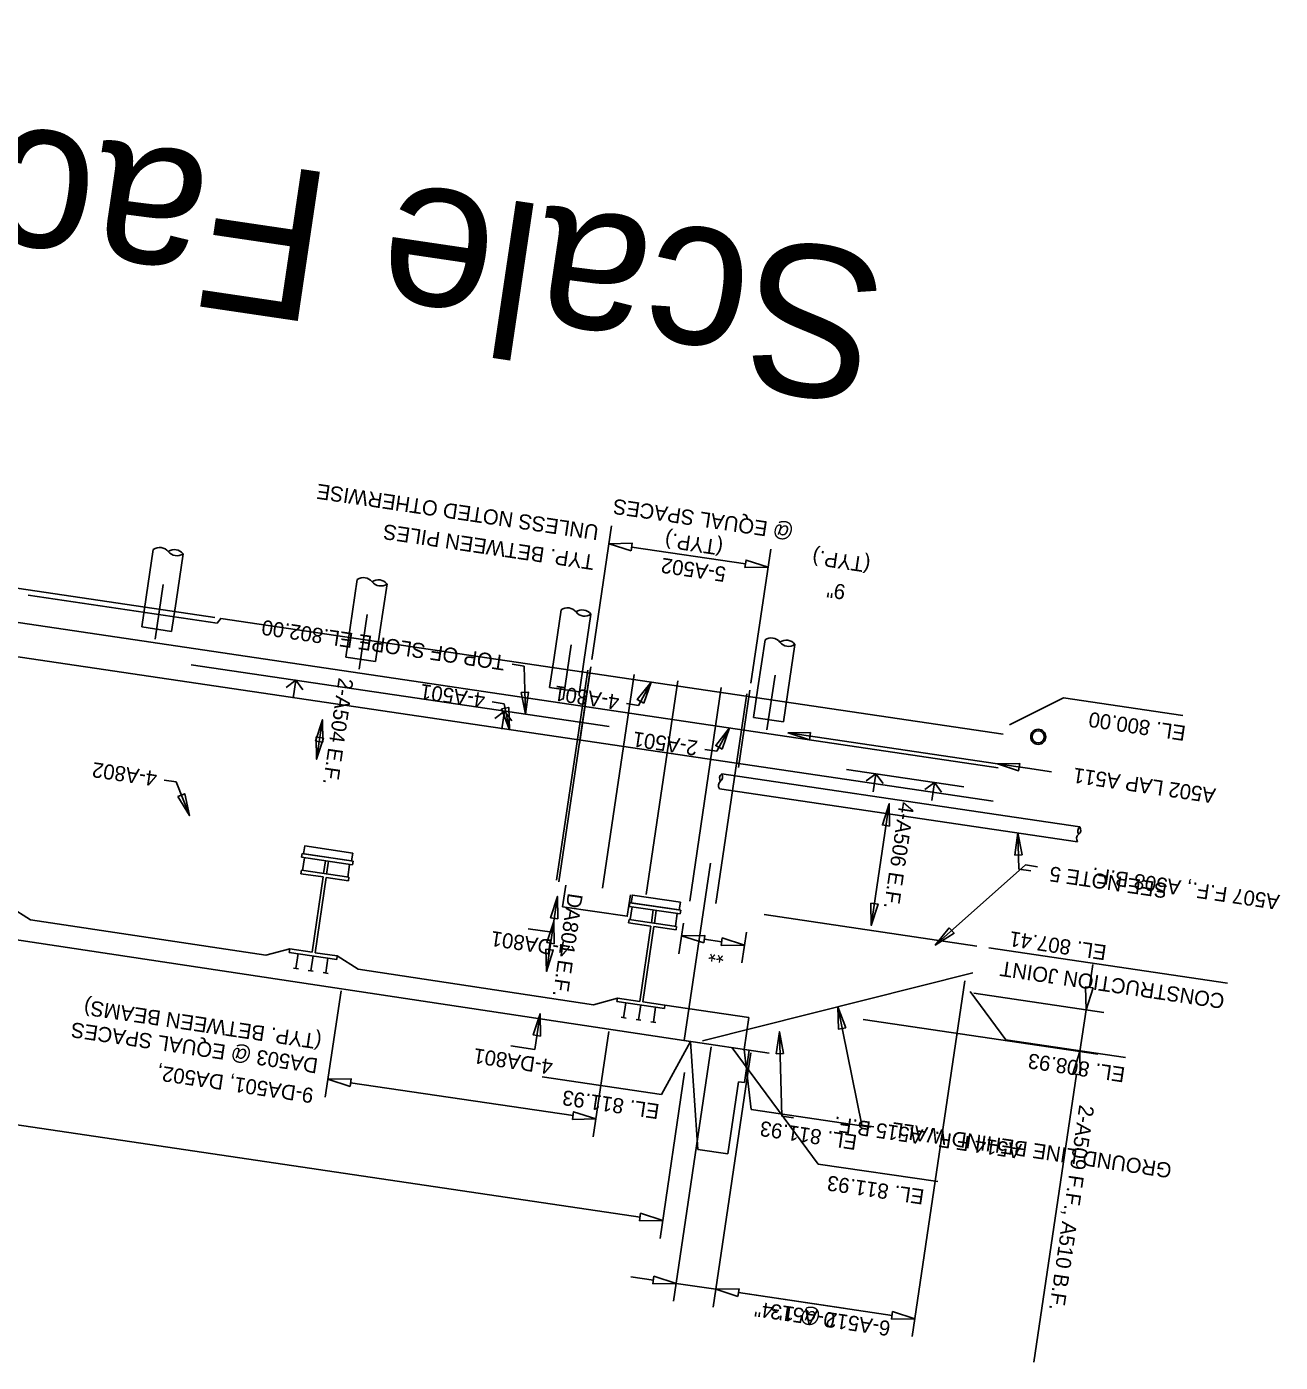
# Model space of a CAD drawing. Extents: x 1468952 to 1470054, y 573916 to 574214.
# Drawn here: x 1469049.93 to 1469091.48, y 574051.68 to 574095.95 of the extents above; entities that cross this region are included whole.
import ezdxf

# ---------------------------------------------------------------- set-up
doc = ezdxf.new("R2010")
doc.units = 0
for name, color, linetype in [('BR_P_Beam_Object', 7, 'Continuous'), ('BR_P_Beam_Stl_Det', 7, 'Continuous'), ('BR_P_Gen_Centerline', 7, 'Continuous'), ('BR_P_Gen_Phase_Construction', 7, 'Continuous'), ('BR_P_Sub_Centerline', 7, 'Continuous'), ('BR_P_Sub_Deep_Centerline', 7, 'Continuous'), ('BR_P_Sub_Foot_Centerline', 7, 'Continuous'), ('BR_X_SV_Beam_Seat', 7, 'Continuous'), ('Default', 7, 'Continuous'), ('GE_P_CL_50', 7, 'Continuous'), ('GK_Cells', 7, 'Continuous'), ('PF_X_Ground_Line', 7, 'Continuous'), ('PV_X_EOP', 7, 'Continuous'), ('SV_X_Text_Elevation', 7, 'Continuous'), ('UT_X_Water', 7, 'Continuous')]:
    doc.layers.add(name, color=color, linetype=linetype)

# ---------------------------------------------------------------- blocks, each defined once
blk = doc.blocks.new('arrowOhio')
at = {"layer": 'Default'}
blk.add_lwpolyline([(0.00381, 0.000635), (0.00381, -0.000635), (0, 0)], close=True, dxfattribs=at)

msp = doc.modelspace()

# ---------------------------------------------------------------- linework, layer by layer
at = {"layer": 'BR_P_Beam_Object'}
for p, q in [((1469082.065, 574069.842), (1469072.965, 574071.189)), ((1469081.992, 574069.347), (1469072.891, 574070.694)), ((1469072.33, 574062.337), (1469081.288, 574064.593))]:
    msp.add_line(p, q, dxfattribs=at)
for centre, start, end in [((1469073.04, 574070.799), 127.976, 215.1816), ((1469073.076, 574071.046), 127.976, 215.1816), ((1469072.817, 574071.085), 307.976, 35.1816)]:
    msp.add_arc(centre, 0.181, start, end, dxfattribs=at)
at = {"layer": 'BR_P_Beam_Stl_Det'}
for p, q in [((1469068.524, 574074.626), (1469067.494, 574067.667)), ((1469068.619, 574074.697), (1469067.57, 574067.614)), ((1469068.625, 574074.738), (1469068.247, 574072.182)), ((1469070.063, 574074.483), (1469069.014, 574067.4)), ((1469071.507, 574074.269), (1469070.458, 574067.186)), ((1469072.951, 574074.055), (1469071.903, 574066.972)), ((1469073.901, 574073.957), (1469073.522, 574071.401)), ((1469073.8, 574073.845), (1469072.77, 574066.886))]:
    msp.add_line(p, q, dxfattribs=at)
for points in [[(1469056.161, 574076.372), (1469030.427, 574080.182), (1469030.303, 574080.026), (1469024.038, 574080.953)], [(1469082.126, 574071.391), (1469046.506, 574076.665), (1469046.433, 574076.85), (1469043.3, 574077.314)], [(1469082.291, 574072.504), (1469056.359, 574076.343), (1469056.235, 574076.186), (1469049.97, 574077.114)], [(1469081.962, 574070.278), (1469046.341, 574075.552), (1469046.268, 574075.738), (1469043.135, 574076.201)]]:
    msp.add_lwpolyline(points, dxfattribs=at)
at = {"layer": 'BR_P_Gen_Centerline'}
for p, q in [((1469082.065, 574069.842), (1469084.835, 574069.432)), ((1469081.992, 574069.347), (1469084.762, 574068.937))]:
    msp.add_line(p, q, dxfattribs=at)
for radius in [0.25, 0.2]:
    msp.add_circle((1469083.457, 574072.416), radius, dxfattribs=at)
for centre, start, end in [((1469084.91, 574069.041), 127.976, 215.1816), ((1469084.947, 574069.289), 127.976, 215.1816), ((1469084.687, 574069.327), 307.976, 35.1816)]:
    msp.add_arc(centre, 0.181, start, end, dxfattribs=at)
at = {"layer": 'BR_P_Gen_Phase_Construction'}
for p, q in [((1469053.887, 574077.046), (1469054.122, 574078.629)), ((1469054.877, 574076.9), (1469055.111, 574078.482)), ((1469060.647, 574076.045), (1469060.881, 574077.628)), ((1469061.636, 574075.899), (1469061.871, 574077.482)), ((1469067.407, 574075.045), (1469067.641, 574076.627)), ((1469068.396, 574074.898), (1469068.63, 574076.481)), ((1469074.166, 574074.044), (1469074.401, 574075.627)), ((1469075.155, 574073.897), (1469075.39, 574075.48))]:
    msp.add_line(p, q, dxfattribs=at)
for centre, start, end in [((1469054.331, 574078.332), 37.976, 125.1816), ((1469054.825, 574078.259), 37.976, 125.1816), ((1469054.902, 574078.779), 217.976, 305.1816), ((1469061.09, 574077.332), 37.976, 125.1816), ((1469061.585, 574077.258), 37.976, 125.1816), ((1469061.662, 574077.778), 217.976, 305.1816), ((1469067.85, 574076.331), 37.976, 125.1816), ((1469068.344, 574076.258), 37.976, 125.1816), ((1469068.421, 574076.777), 217.976, 305.1816), ((1469074.609, 574075.33), 37.976, 125.1816), ((1469075.104, 574075.257), 37.976, 125.1816), ((1469075.181, 574075.776), 217.976, 305.1816)]:
    msp.add_arc(centre, 0.362, start, end, dxfattribs=at)
at = {"layer": 'BR_P_Sub_Centerline'}
for p, q in [((1469053.741, 574076.057), (1469053.887, 574077.046)), ((1469054.877, 574076.9), (1469054.73, 574075.91)), ((1469054.73, 574075.91), (1469053.741, 574076.057)), ((1469060.501, 574075.056), (1469060.647, 574076.045)), ((1469061.636, 574075.899), (1469061.49, 574074.91)), ((1469061.49, 574074.91), (1469060.501, 574075.056)), ((1469067.26, 574074.055), (1469067.407, 574075.045)), ((1469068.396, 574074.898), (1469068.249, 574073.909)), ((1469068.249, 574073.909), (1469067.26, 574074.055)), ((1469074.02, 574073.055), (1469074.166, 574074.044)), ((1469075.155, 574073.897), (1469075.009, 574072.908)), ((1469075.009, 574072.908), (1469074.02, 574073.055))]:
    msp.add_line(p, q, dxfattribs=at)
at = {"layer": 'BR_P_Sub_Deep_Centerline'}
for q in [(1469072.594, 574068.231), (1469074.541, 574061.928)]:
    msp.add_line((1469071.723, 574062.345), q, dxfattribs=at)
at = {"layer": 'BR_P_Sub_Foot_Centerline'}
for p, q in [((1469059.073, 574067.986), (1469059.136, 574068.409)), ((1469059.77, 574067.883), (1469059.833, 574068.306)), ((1469059.869, 574067.868), (1469059.932, 574068.291)), ((1469060.566, 574067.765), (1469060.629, 574068.188)), ((1469069.936, 574066.358), (1469069.998, 574066.78)), ((1469070.633, 574066.255), (1469070.695, 574066.677)), ((1469070.732, 574066.24), (1469070.794, 574066.663)), ((1469071.429, 574066.137), (1469071.491, 574066.559))]:
    msp.add_line(p, q, dxfattribs=at)
at = {"layer": 'BR_X_SV_Beam_Seat'}
for p, q in [((1469069.23, 574072.753), (1469055.381, 574074.803)), ((1469058.844, 574074.29), (1469058.522, 574074.052)), ((1469058.844, 574074.29), (1469058.756, 574073.697)), ((1469058.844, 574074.29), (1469059.082, 574073.969)), ((1469065.768, 574073.265), (1469065.447, 574073.027)), ((1469065.768, 574073.265), (1469065.68, 574072.672)), ((1469065.768, 574073.265), (1469066.006, 574072.944)), ((1469080.988, 574070.759), (1469077.107, 574071.334)), ((1469078.078, 574071.19), (1469077.756, 574070.952)), ((1469078.078, 574071.19), (1469077.99, 574070.597)), ((1469078.078, 574071.19), (1469078.316, 574070.869)), ((1469080.018, 574070.903), (1469079.697, 574070.665)), ((1469080.018, 574070.903), (1469079.93, 574070.309)), ((1469080.018, 574070.903), (1469080.256, 574070.582)), ((1469081.815, 574065.421), (1469089.729, 574064.249))]:
    msp.add_line(p, q, dxfattribs=at)
msp.add_lwpolyline([(1469069.941, 574067.179), (1469069.836, 574066.468), (1469067.692, 574066.785), (1469067.798, 574067.496)], dxfattribs=at)
at = {"layer": 'GE_P_CL_50'}
for p, q in [((1469059.145, 574068.797), (1469059.107, 574068.539)), ((1469059.039, 574068.423), (1469059.057, 574068.547)), ((1469060.726, 574068.173), (1469059.039, 574068.423)), ((1469059.057, 574068.547), (1469060.744, 574068.297)), ((1469060.733, 574068.562), (1469060.694, 574068.304)), ((1469060.744, 574068.297), (1469060.726, 574068.173)), ((1469069.901, 574066.795), (1469069.92, 574066.918)), ((1469069.92, 574066.918), (1469071.606, 574066.669)), ((1469070.007, 574067.169), (1469069.969, 574066.911)), ((1469071.595, 574066.934), (1469071.557, 574066.676)), ((1469071.588, 574066.545), (1469069.901, 574066.795)), ((1469071.606, 574066.669), (1469071.588, 574066.545))]:
    msp.add_line(p, q, dxfattribs=at)
for points in [[(1469060.733, 574068.562), (1469060.694, 574068.304), (1469059.107, 574068.539), (1469059.145, 574068.797)], [(1469071.595, 574066.934), (1469071.557, 574066.676), (1469069.969, 574066.911), (1469070.007, 574067.169)]]:
    msp.add_lwpolyline(points, close=True, dxfattribs=at)
at = {"layer": 'GK_Cells'}
for p, q in [((1469059.015, 574067.879), (1469059.032, 574067.992)), ((1469059.753, 574067.77), (1469059.015, 574067.879)), ((1469059.032, 574067.992), (1469060.607, 574067.759)), ((1469059.384, 574065.276), (1469059.753, 574067.77)), ((1469059.853, 574067.755), (1469059.483, 574065.261)), ((1469060.591, 574067.646), (1469059.853, 574067.755)), ((1469060.607, 574067.759), (1469060.591, 574067.646)), ((1469069.878, 574066.251), (1469069.895, 574066.364)), ((1469070.616, 574066.141), (1469069.878, 574066.251)), ((1469069.895, 574066.364), (1469071.47, 574066.131)), ((1469070.247, 574063.648), (1469070.616, 574066.141)), ((1469070.715, 574066.127), (1469070.346, 574063.633)), ((1469071.453, 574066.018), (1469070.715, 574066.127)), ((1469071.47, 574066.131), (1469071.453, 574066.018)), ((1469058.629, 574065.272), (1469058.646, 574065.385)), ((1469060.205, 574065.039), (1469058.629, 574065.272)), ((1469058.646, 574065.385), (1469059.384, 574065.276)), ((1469058.922, 574065.229), (1469058.849, 574064.734)), ((1469059.417, 574065.155), (1469059.344, 574064.661)), ((1469059.483, 574065.261), (1469060.221, 574065.152)), ((1469059.912, 574065.082), (1469059.838, 574064.588)), ((1469060.221, 574065.152), (1469060.205, 574065.039)), ((1469058.932, 574064.722), (1469058.767, 574064.746)), ((1469059.426, 574064.649), (1469059.261, 574064.673)), ((1469059.921, 574064.575), (1469059.756, 574064.6)), ((1469069.492, 574063.644), (1469069.509, 574063.757)), ((1469069.509, 574063.757), (1469070.247, 574063.648)), ((1469071.067, 574063.411), (1469069.492, 574063.644)), ((1469069.785, 574063.6), (1469069.712, 574063.106)), ((1469070.279, 574063.527), (1469070.206, 574063.033)), ((1469070.346, 574063.633), (1469071.084, 574063.524)), ((1469070.774, 574063.454), (1469070.701, 574062.959)), ((1469071.084, 574063.524), (1469071.067, 574063.411)), ((1469069.794, 574063.094), (1469069.629, 574063.118)), ((1469070.289, 574063.02), (1469070.124, 574063.045)), ((1469070.783, 574062.947), (1469070.618, 574062.972))]:
    msp.add_line(p, q, dxfattribs=at)
at = {"layer": 'PF_X_Ground_Line'}
for p, q in [((1469071.925, 574062.316), (1469040.98, 574066.988)), ((1469073.868, 574063.112), (1469071.084, 574063.524)), ((1469073.711, 574062.048), (1469073.868, 574063.112)), ((1469071.925, 574062.316), (1469072.173, 574058.741)), ((1469071.925, 574062.316), (1469071.925, 574062.316)), ((1469071.925, 574062.316), (1469071.925, 574062.316)), ((1469073.876, 574062.027), (1469073.711, 574062.051)), ((1469073.718, 574060.955), (1469073.876, 574062.027)), ((1469073.165, 574058.594), (1469073.519, 574060.984)), ((1469073.519, 574060.984), (1469073.718, 574060.955)), ((1469072.173, 574058.741), (1469073.165, 574058.594))]:
    msp.add_line(p, q, dxfattribs=at)
for points in [[(1469058.646, 574065.385), (1469057.857, 574065.177), (1469050.054, 574066.355), (1469049.36, 574066.79)], [(1469069.509, 574063.757), (1469068.718, 574063.537), (1469060.915, 574064.715), (1469060.221, 574065.152)]]:
    msp.add_lwpolyline(points, dxfattribs=at)
at = {"layer": 'PV_X_EOP'}
msp.add_line((1469081.42, 574065.479), (1469074.373, 574066.522), dxfattribs=at)
at = {"layer": 'SV_X_Text_Elevation'}
for p, q in [((1469068.66, 574074.975), (1469069.317, 574079.412)), ((1469073.753, 574078.149), (1469069.981, 574078.707)), ((1469073.936, 574074.194), (1469074.593, 574078.631)), ((1469066.416, 574074.762), (1469066.021, 574074.821)), ((1469066.461, 574073.163), (1469066.416, 574074.762)), ((1469070.622, 574074.232), (1469070.203, 574073.458)), ((1469065.756, 574073.513), (1469065.36, 574073.572)), ((1469065.933, 574072.651), (1469065.756, 574073.513)), ((1469070.203, 574073.458), (1469069.807, 574073.516)), ((1469082.505, 574072.809), (1469084.293, 574073.704)), ((1469084.293, 574073.704), (1469088.25, 574073.118)), ((1469059.729, 574072.98), (1469059.535, 574071.671)), ((1469073.221, 574072.709), (1469072.802, 574071.936)), ((1469075.166, 574072.548), (1469082.103, 574071.521)), ((1469072.802, 574071.936), (1469072.407, 574071.994)), ((1469082.103, 574071.521), (1469083.101, 574071.373)), ((1469082.103, 574071.521), (1469082.103, 574071.521)), ((1469083.101, 574071.373), (1469083.892, 574071.256)), ((1469054.879, 574070.92), (1469054.484, 574070.979)), ((1469055.321, 574069.804), (1469054.879, 574070.92)), ((1469070.259, 574056.497), (1468978.025, 574070.152)), ((1469078.518, 574070.198), (1469077.921, 574066.166)), ((1469082.784, 574069.23), (1469082.817, 574068.03)), ((1469080.043, 574065.514), (1469083.035, 574068.169)), ((1469083.035, 574068.169), (1469083.431, 574068.11)), ((1469082.817, 574068.03), (1469083.212, 574067.972)), ((1469067.52, 574067.124), (1469067.344, 574065.937)), ((1469067.344, 574065.937), (1469066.552, 574066.054)), ((1469067.397, 574066.297), (1469067.152, 574064.642)), ((1469071.698, 574066.244), (1469071.547, 574065.228)), ((1469073.782, 574065.943), (1469073.631, 574064.919)), ((1469072.967, 574065.624), (1469072.387, 574065.71)), ((1469085.154, 574064.115), (1469085.265, 574064.867)), ((1469081.024, 574064.332), (1469079.277, 574052.533)), ((1469060.345, 574063.991), (1469059.823, 574060.47)), ((1469081.197, 574063.976), (1469082.389, 574062.37)), ((1469081.323, 574063.914), (1469085.636, 574063.276)), ((1469076.809, 574063.465), (1469077.612, 574059.546)), ((1469085.043, 574063.364), (1469084.838, 574061.983)), ((1469066.944, 574063.238), (1469066.768, 574062.051)), ((1469077.653, 574063.047), (1469085.432, 574061.895)), ((1469069.218, 574062.652), (1469068.7, 574059.155)), ((1469074.877, 574062.641), (1469074.955, 574059.842)), ((1469066.768, 574062.051), (1469065.977, 574062.168)), ((1469071.925, 574062.316), (1469070.973, 574060.557)), ((1469072.612, 574062.14), (1469071.363, 574053.705)), ((1469073.308, 574062.111), (1469076.168, 574058.256)), ((1469073.711, 574062.051), (1469073.941, 574060.064)), ((1469082.389, 574062.37), (1469086.346, 574061.784)), ((1469073.931, 574061.944), (1469072.682, 574053.51)), ((1469073.931, 574061.944), (1469072.682, 574053.51)), ((1469070.973, 574060.557), (1469067.017, 574061.142)), ((1469071.737, 574061.289), (1469070.923, 574055.792)), ((1469084.727, 574061.231), (1469083.314, 574051.684)), ((1469068.037, 574059.86), (1469060.663, 574060.952)), ((1469073.941, 574060.064), (1469077.897, 574059.478)), ((1469074.955, 574059.842), (1469075.35, 574059.784)), ((1469077.612, 574059.546), (1469078.008, 574059.488)), ((1469076.168, 574058.256), (1469080.125, 574057.671)), ((1469070.699, 574054.41), (1469069.948, 574054.521)), ((1469071.451, 574054.299), (1469072.77, 574054.103)), ((1469073.522, 574053.992), (1469078.613, 574053.238)), ((1469073.522, 574053.992), (1469076.997, 574053.478))]:
    msp.add_line(p, q, dxfattribs=at)
for points in [[(1469069.962, 574078.582), (1469069.999, 574078.832), (1469069.229, 574078.818)], [(1469073.734, 574078.023), (1469073.772, 574078.274), (1469074.505, 574078.037)], [(1469072.368, 574065.585), (1469072.405, 574065.835), (1469071.635, 574065.821)], [(1469072.948, 574065.499), (1469072.985, 574065.749), (1469073.718, 574065.513)], [(1469085.279, 574064.097), (1469085.029, 574064.134), (1469085.043, 574063.364)], [(1469084.852, 574061.213), (1469084.602, 574061.25), (1469084.838, 574061.983)], [(1469060.645, 574060.827), (1469060.682, 574061.077), (1469059.911, 574061.063)], [(1469068.018, 574059.735), (1469068.055, 574059.986), (1469068.788, 574059.749)], [(1469070.241, 574056.372), (1469070.278, 574056.622), (1469071.011, 574056.386)], [(1469070.681, 574054.285), (1469070.718, 574054.535), (1469071.451, 574054.299)], [(1469073.503, 574053.867), (1469073.541, 574054.117), (1469072.77, 574054.103)], [(1469073.503, 574053.867), (1469073.541, 574054.117), (1469072.77, 574054.103)], [(1469078.595, 574053.113), (1469078.632, 574053.364), (1469079.365, 574053.127)]]:
    msp.add_lwpolyline(points, close=True, dxfattribs=at)
at = {"layer": 'UT_X_Water'}
for p, q in [((1469054.187, 574075.654), (1469054.455, 574077.467)), ((1469060.946, 574074.653), (1469061.215, 574076.467)), ((1469067.706, 574073.652), (1469067.974, 574075.466)), ((1469074.466, 574072.652), (1469074.734, 574074.465))]:
    msp.add_line(p, q, dxfattribs=at)

# ---------------------------------------------------------------- block references
at = {"layer": 'SV_X_Text_Elevation'}
for p, xscale, yscale, rotation in [((1469070.622, 574074.232), 191.49568, 191.49568000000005, -118.42123067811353), ((1469066.461, 574073.163), 191.49568, 191.49568, 91.57876932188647), ((1469065.933, 574072.651), 191.49568000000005, 191.49568, 101.57876932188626), ((1469059.729, 574072.98), 191.49568000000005, 191.49568, -98.42123067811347), ((1469073.221, 574072.709), 191.49568, 191.49568000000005, -118.42123067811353), ((1469075.166, 574072.548), 191.49568000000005, 191.49568, -8.421230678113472), ((1469059.535, 574071.671), 191.49568000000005, 191.49568, 81.57876932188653), ((1469082.103, 574071.521), 191.49568000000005, 191.49568, -8.421230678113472), ((1469055.321, 574069.804), 191.49568000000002, 191.49568000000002, 111.57876932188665), ((1469078.518, 574070.198), 191.49568000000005, 191.49568, -98.42123067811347), ((1469082.784, 574069.23), 191.49568000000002, 191.49568000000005, -88.42123067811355), ((1469067.52, 574067.124), 191.49568000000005, 191.49568, -98.42123067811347), ((1469077.921, 574066.166), 191.49568000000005, 191.49568, 81.57876932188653), ((1469067.397, 574066.297), 191.49568000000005, 191.49568, -98.42123067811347), ((1469080.043, 574065.514), 191.49568000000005, 191.49568, 41.57876932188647), ((1469067.152, 574064.642), 191.49568000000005, 191.49568, 81.57876932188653), ((1469076.809, 574063.465), 191.49568000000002, 191.49568000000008, -78.42123067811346), ((1469066.944, 574063.238), 191.49568000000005, 191.49568, -98.42123067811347), ((1469074.877, 574062.641), 191.49568, 191.49568000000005, -88.42123067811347)]:
    msp.add_blockref('arrowOhio', p, dxfattribs=dict(at, xscale=xscale, yscale=yscale, rotation=rotation))

# ---------------------------------------------------------------- texts
for s, height, rotation, p in [('Scale Factor = 48', 4.99999, 171.5788, (1469078.57, 574088.343)), ('UNLESS NOTED OTHERWISE', 0.5, 171.5788, (1469068.914, 574079.425)), (' @ EQUAL SPACES', 0.5, 171.5788, (1469075.553, 574079.398)), ('TYP. BETWEEN PILES', 0.5, 171.5788, (1469068.768, 574078.436)), ('(TYP.)', 0.5, 171.5788, (1469073.032, 574078.912)), ('5-A502', 0.5, 171.5788, (1469073.131, 574078.038)), ('(TYP.)', 0.5, 171.5788, (1469077.918, 574078.341)), ('9"', 0.5, 171.5788, (1469077.094, 574077.452)), ('TOP OF SLOPE EL.802.00', 0.5, 171.5788, (1469065.81, 574075.105)), ('2-A504 E.F.', 0.5, 261.5788, (1469060.267, 574074.39)), ('4-A501', 0.5, 171.5788, (1469065.149, 574073.856)), ('4-A801', 0.5, 171.5788, (1469069.596, 574073.8)), ('EL. 800.00', 0.5, 171.5788, (1469088.373, 574072.771)), ('2-A501', 0.5, 171.5788, (1469072.196, 574072.278)), ('4-A802', 0.5, 171.5788, (1469054.273, 574071.263)), ('A502 LAP A511', 0.5, 171.5788, (1469089.366, 574070.698)), ('4-A506 E.F.', 0.5, 261.5788, (1469078.859, 574070.279)), ('SEE NOTE 5', 0.5, 171.5788, (1469087.769, 574067.55)), ('A507 F.F., A508 B.F.', 0.5, 171.5788, (1469091.483, 574067.171)), ('DA801 E.F.', 0.5, 261.5788, (1469067.868, 574067.254)), ('4-DA801', 0.5, 171.5788, (1469067.968, 574065.596)), ('EL. 807.41', 0.5, 171.5788, (1469085.746, 574065.5)), ('**', 0.5, 171.5788, (1469073.089, 574065.404)), ('CONSTRUCTION JOINT', 0.5, 171.5788, (1469089.659, 574063.889)), ('(TYP. BETWEEN BEAMS)', 0.5, 171.5788, (1469059.726, 574062.54)), ('DA503 @ EQUAL SPACES', 0.5, 171.5788, (1469059.608, 574061.749)), ('4-DA801', 0.5, 171.5788, (1469067.392, 574061.71)), ('9-DA501, DA502,', 0.5, 171.5788, (1469059.462, 574060.76)), ('EL. 808.93', 0.5, 171.5788, (1469086.363, 574061.452)), ('EL. 811.93', 0.5, 171.5788, (1469070.926, 574060.234)), ('2-A509 F.F., A510 B.F.', 0.5, 261.5788, (1469084.823, 574060.235)), ('A514 F.F., A515 B.F.', 0.5, 171.5788, (1469082.932, 574058.914)), ('EL. 811.93', 0.5, 171.5788, (1469077.477, 574059.211)), ('GROUND LINE BEHIND WALL', 0.5, 171.5788, (1469087.908, 574058.275)), ('EL. 811.93', 0.5, 171.5788, (1469079.704, 574057.403)), ('6-A512 @ 1\'-4"', 0.5, 171.5788, (1469078.584, 574053.04)), ('0-A513', 0.5, 171.5788, (1469076.751, 574053.312))]:
    msp.add_text(s, height=height, rotation=rotation, dxfattribs=at).set_placement(p)

doc.saveas('drawing.dxf')
